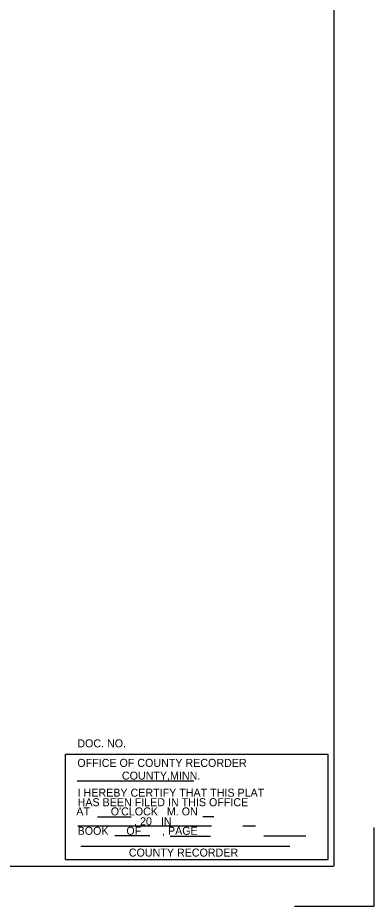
# Model space of a CAD drawing. Extents: x 2147712 to 2176316, y 2125036 to 2131746.
# Drawn here: x 2174553 to 2174999, y 2127109 to 2128219 of the extents above; entities that cross this region are included whole.
import ezdxf

# ---------------------------------------------------------------- set-up
doc = ezdxf.new("R2010")
doc.units = 0
for name, color, linetype in [('PLAT INFO', 7, 'Continuous'), ('PLOT AIDS', 7, 'Continuous'), ('SHT BRDR', 7, 'Continuous')]:
    doc.layers.add(name, color=color, linetype=linetype)

msp = doc.modelspace()

# ---------------------------------------------------------------- linework, layer by layer
at = {"layer": 'PLAT INFO'}
for p, q in [((2174613, 2127167.7), (2174613, 2127299.3)), ((2174613, 2127299.3), (2174941.3, 2127299.3)), ((2174941.3, 2127167.7), (2174941.3, 2127299.3)), ((2174627.4, 2127265.9), (2174773.5, 2127265.9)), ((2174653, 2127220.8), (2174695.1, 2127220.8)), ((2174798.2, 2127220.8), (2174784.5, 2127220.8)), ((2174628.3, 2127209.9), (2174795.6, 2127209.9)), ((2174834.6, 2127209.6), (2174850.3, 2127209.6)), ((2174674.4, 2127197.5), (2174718.5, 2127197.5)), ((2174743.6, 2127196.9), (2174794.1, 2127196.9)), ((2174860.7, 2127197.2), (2174913.3, 2127197.2)), ((2174632.1, 2127184.1), (2174893.3, 2127184.1)), ((2174613, 2127167.7), (2174941.3, 2127167.7))]:
    msp.add_line(p, q, dxfattribs=at)
at = {"layer": 'PLOT AIDS'}
for p, q in [((2174998.9, 2127109.3), (2174998.9, 2127207.6)), ((2174899.1, 2127109.3), (2174998.9, 2127109.3))]:
    msp.add_line(p, q, dxfattribs=at)
at = {"layer": 'SHT BRDR'}
for p, q in [((2174948.9, 2127159.3), (2174948.9, 2129267.8)), ((2171797.9, 2127159.3), (2174947.9, 2127159.3))]:
    msp.add_line(p, q, dxfattribs=at)

# ---------------------------------------------------------------- texts
at = {"layer": 'PLAT INFO'}
for s, p in [('DOC. NO.                ', (2174627.7, 2127307.7)), ('OFFICE OF COUNTY RECORDER ', (2174627.7, 2127283.3)), ('               COUNTY,MINN.', (2174627.7, 2127267.4)), ('I HEREBY CERTIFY THAT THIS PLAT', (2174628.1, 2127246.1)), ('HAS BEEN FILED IN THIS OFFICE', (2174628.1, 2127234.2)), ("AT       O'CLOCK   M. ON", (2174626.4, 2127222.7)), ('                   , 20   IN', (2174628.1, 2127210.4)), ('BOOK      OF       , PAGE     ', (2174628.1, 2127198.5)), ('COUNTY RECORDER', (2174692.1, 2127171.3))]:
    msp.add_text(s, height=10, dxfattribs=at).set_placement(p)

doc.saveas('drawing.dxf')
